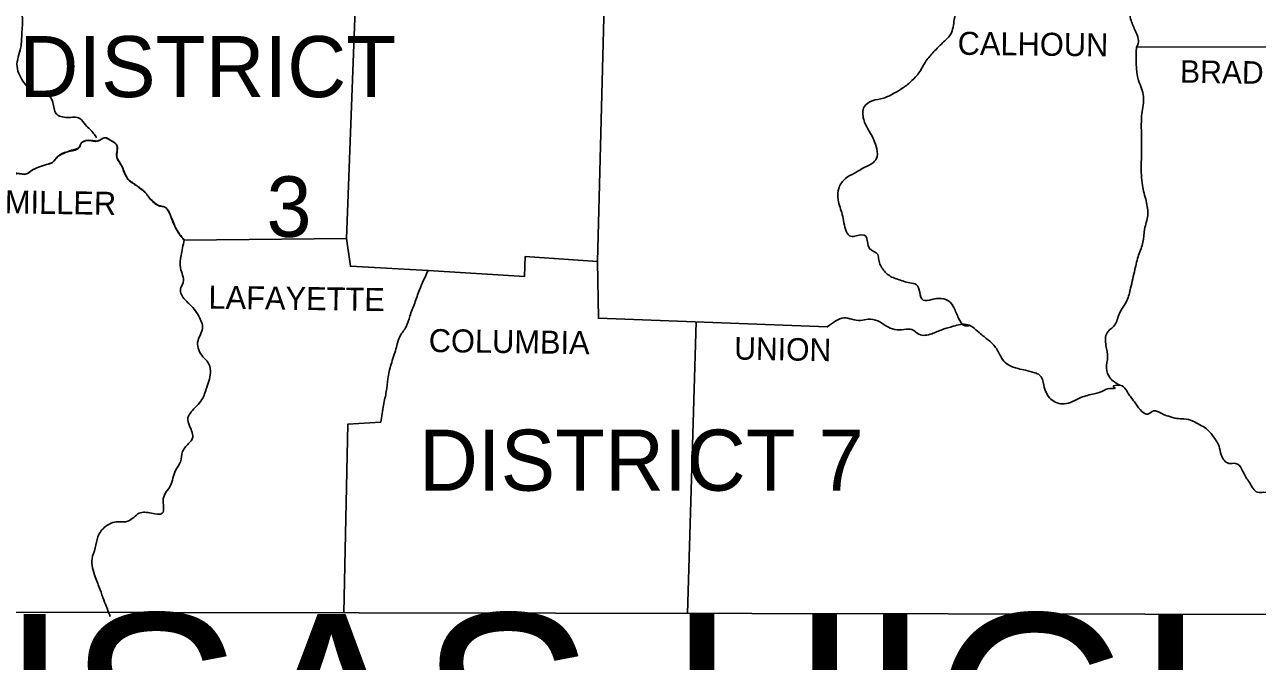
# Model space of a CAD drawing. Extents: x 3046 to 131673, y -8885 to 10756.
# Drawn here: x 64530 to 66781, y 4994 to 6157 of the extents above; entities that cross this region are included whole.
import ezdxf

# ---------------------------------------------------------------- set-up
doc = ezdxf.new("R2010")
doc.units = 0
for name, color, linetype in [('1', 7, 'Continuous'), ('2', 7, 'Continuous'), ('3', 7, 'Continuous'), ('R_Annotation', 7, 'Continuous')]:
    doc.layers.add(name, color=color, linetype=linetype)

msp = doc.modelspace()

# ---------------------------------------------------------------- linework, layer by layer
at = {"layer": '1'}
for points in [[(65157.419338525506, 6478.611953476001), (65155.46252490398, 6283.908996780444), (65137.851202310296, 6281.952183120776), (65118.283065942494, 5766.331790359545)], [(65588.89674506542, 6217.377333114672), (65576.17745635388, 5724.260297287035), (65444.09253611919, 5733.06595852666), (65443.11412921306, 5696.86490635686), (65267.00090220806, 5707.62738140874)], [(66560.45471461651, 6115.623024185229), (67002.69459609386, 6116.601431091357)], [(64421.65741198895, 5874.934947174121), (64423.614225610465, 5083.403831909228), (68009.47521109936, 5077.533390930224)], [(65267.00090220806, 5707.62738140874), (65125.13191359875, 5715.454635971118), (65118.283065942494, 5766.331790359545), (64821.82580016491, 5763.396570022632)], [(65995.91398108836, 5604.894665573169), (65578.13427001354, 5620.54917462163), (65576.08045633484, 5724.266763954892)], [(65756.26641412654, 5613.874433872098), (65740.74359051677, 5081.247549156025)], [(65180.901102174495, 5430.73825199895), (65120.23987956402, 5426.824624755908), (65113.391031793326, 5082.425425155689)]]:
    msp.add_lwpolyline(points, dxfattribs=at)
for points in [[(64352.190527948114, 6825.946373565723), (64357.08256194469, 6796.594169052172), (64365.8882234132, 6771.155591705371), (64366.86663012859, 6751.587455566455), (64375.6722915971, 6722.2352509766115), (64375.6722915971, 6711.472775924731), (64378.607512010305, 6689.947825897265), (64374.69388469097, 6678.2069442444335), (64379.585918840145, 6654.7251806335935), (64378.607512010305, 6637.11385784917), (64378.607512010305, 6622.437755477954), (64379.585918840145, 6597.977585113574), (64387.41317324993, 6576.452635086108), (64395.24042777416, 6544.16521015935), (64400.13246199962, 6527.532294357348), (64407.95971652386, 6502.09371708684), (64412.851750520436, 6470.7846988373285), (64413.830157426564, 6447.302935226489), (64411.87334380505, 6425.777985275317), (64417.7437847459, 6401.317814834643), (64428.5062596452, 6376.857644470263), (64442.203955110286, 6353.375880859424), (64458.83687095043, 6326.9588968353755), (64470.57775275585, 6306.41235356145), (64485.25385512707, 6283.908996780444), (64496.99473693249, 6265.319267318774), (64514.606059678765, 6241.837503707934), (64522.433314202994, 6222.2693672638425), (64522.433314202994, 6194.873976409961), (64526.3469413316, 6169.435399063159), (64525.368534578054, 6141.061601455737), (64523.41172095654, 6115.623024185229), (64516.56287330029, 6080.400378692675), (64521.454907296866, 6063.767462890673), (64540.04463679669, 6039.307292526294), (64551.785518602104, 6032.458444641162), (64572.33206187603, 6028.544817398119), (64582.11613005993, 6014.847121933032), (64587.98657096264, 5994.300578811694), (64608.53311408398, 5987.451731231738), (64631.03647082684, 5985.49491757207), (64641.79894587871, 5973.75403576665), (64656.475048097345, 5958.099526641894), (64661.36708228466, 5950.272272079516)], [(66381.40626708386, 6507.964157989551), (66403.90962378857, 6493.2880556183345), (66422.49935344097, 6473.719919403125), (66436.19704890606, 6459.0438170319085), (66445.00271018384, 6442.410901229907), (66456.7435920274, 6422.842764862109), (66473.3765078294, 6385.663305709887), (66488.05261020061, 6372.944017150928), (66508.59915332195, 6360.22472843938), (66521.31844207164, 6351.419067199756), (66534.03773059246, 6323.04526951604), (66539.90817149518, 6294.671471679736), (66550.67064643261, 6269.23289463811), (66555.56268058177, 6249.664758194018), (66546.75701915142, 6230.096621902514), (66544.8002055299, 6190.960349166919), (66550.67064643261, 6164.543365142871), (66558.49790099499, 6144.975228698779), (66563.3899351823, 6122.471871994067), (66560.45471461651, 6115.623024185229)], [(66237.08427846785, 6257.806639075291), (66234.64524447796, 6196.830789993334), (66227.79639682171, 6166.5001787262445), (66220.94754901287, 6139.104787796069), (66206.27144683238, 6123.450278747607), (66190.61693770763, 6107.795769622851), (66175.94083552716, 6090.184446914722), (66163.2215468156, 6068.659496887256), (66150.50225825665, 6054.961801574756), (66133.86934222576, 6041.264106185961), (66117.23642638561, 6031.4800379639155), (66098.6466969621, 6022.67437649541), (66078.10015365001, 6017.782342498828), (66063.42405146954, 6007.019867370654), (66062.44564456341, 5983.538103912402), (66079.07856055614, 5950.272272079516), (66084.949001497, 5934.61776295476), (66086.90581515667, 5916.028033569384), (66080.05696730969, 5905.2655584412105), (66064.40245818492, 5896.459897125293), (66045.8127287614, 5885.697422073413), (66029.17981292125, 5875.913353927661), (66017.43893111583, 5859.280438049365), (66015.48211745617, 5836.777081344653), (66023.3093719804, 5810.360097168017), (66026.24459235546, 5794.705588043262), (66038.96388110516, 5770.245417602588), (66048.7479492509, 5771.223824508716), (66066.3592718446, 5770.245417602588), (66068.31608550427, 5765.3533836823), (66069.2944924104, 5760.461349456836), (66073.20811969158, 5747.7420608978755), (66087.88422187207, 5736.979585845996), (66089.84103549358, 5727.19551762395), (66098.6466969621, 5708.60578816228), (66113.32279914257, 5695.88649960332), (66124.08527408, 5691.972872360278), (66146.58863097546, 5685.12402455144), (66158.32951278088, 5682.188804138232), (66171.04880133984, 5653.815006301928), (66186.70331042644, 5654.793413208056), (66198.44419223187, 5656.750226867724), (66218.01232863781, 5651.858192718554), (66226.81798991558, 5640.117311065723), (66235.62365138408, 5620.54917462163), (66247.36453318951, 5606.851479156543), (66255.19178771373, 5606.851479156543)], [(66560.45471461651, 6115.623024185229), (66564.3683418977, 6054.961801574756), (66573.17400332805, 6025.609597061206), (66570.23878280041, 5994.300578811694), (66569.26037604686, 5963.9699675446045), (66569.26037604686, 5936.574576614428), (66569.26037604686, 5910.157592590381), (66569.26037604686, 5882.7622016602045), (66571.21718970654, 5863.194065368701), (66578.06603736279, 5834.820267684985), (66581.00125792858, 5808.403283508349), (66575.13081698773, 5782.9647063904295), (66572.19559642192, 5759.4829427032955), (66564.3683418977, 5736.0011790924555), (66557.51949424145, 5709.584195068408), (66549.69223971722, 5675.339956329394), (66542.84339187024, 5652.836599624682), (66529.14569659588, 5629.354835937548), (66520.34003516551, 5607.829885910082), (66506.64233970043, 5594.132190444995), (66504.68552604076, 5570.650426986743), (66507.62074660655, 5549.125477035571), (66505.66393294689, 5529.557340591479), (66512.512780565, 5510.967610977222), (66530.12410331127, 5498.2483224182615)], [(64421.65741198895, 5874.934947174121), (64455.90165057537, 5889.611049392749), (64470.57775275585, 5884.719015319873), (64483.2970414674, 5871.999726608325), (64497.97314368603, 5871.999726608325), (64505.80039821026, 5883.740608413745), (64520.47650058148, 5884.719015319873), (64532.2173822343, 5883.740608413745), (64544.936670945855, 5891.567862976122), (64555.69914588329, 5896.459897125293), (64570.37524825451, 5901.351931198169), (64581.1377231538, 5905.2655584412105), (64590.9217913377, 5916.028033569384), (64608.53311408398, 5924.833694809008), (64629.07965716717, 5931.682542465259), (64634.95009810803, 5941.466610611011), (64644.73416629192, 5945.380237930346), (64664.30230265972, 5944.401831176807), (64677.02159121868, 5950.272272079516), (64687.78406630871, 5945.380237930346), (64697.56813445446, 5938.531390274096), (64699.52494811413, 5913.092813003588), (64707.352202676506, 5899.395117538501), (64719.09308452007, 5874.934947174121), (64735.726000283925, 5862.215658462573), (64751.380509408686, 5849.496369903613), (64757.25095034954, 5841.669115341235), (64773.88386618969, 5826.993013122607), (64788.55996852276, 5822.100978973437), (64795.408816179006, 5811.338503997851), (64806.1712910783, 5785.899926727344), (64821.82580016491, 5763.396570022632)], [(64821.82580016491, 5763.396570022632), (64815.955359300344, 5735.0227721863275), (64814.97695254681, 5712.519415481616), (64819.86898654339, 5686.102431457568), (64814.97695254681, 5673.38314274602), (64822.804207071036, 5654.793413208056), (64837.48030928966, 5640.117311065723), (64848.24278434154, 5624.4628019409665), (64855.09163203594, 5601.959445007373), (64846.285970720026, 5576.520867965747), (64856.07003894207, 5550.103883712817), (64864.87570018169, 5540.319815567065), (64869.767734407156, 5524.665306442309), (64862.918886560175, 5494.334695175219), (64854.1132252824, 5471.831338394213), (64834.5450889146, 5449.327981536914), (64828.674648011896, 5438.565506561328), (64831.60986834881, 5423.889404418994), (64836.501902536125, 5400.40764073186), (64831.60986834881, 5393.558792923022), (64818.89057978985, 5376.92587712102), (64814.97695254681, 5358.33614765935), (64806.1712910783, 5342.681638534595), (64796.387223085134, 5314.30784069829), (64783.66793433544, 5290.826077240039), (64781.711120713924, 5264.409093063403), (64762.142984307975, 5264.409093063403), (64739.63962760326, 5264.409093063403), (64719.09308452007, 5249.7329908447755), (64700.503354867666, 5248.754583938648), (64677.99999812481, 5239.948922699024), (64664.30230265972, 5221.359193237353), (64659.41026862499, 5200.812649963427), (64653.539827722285, 5181.2445135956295), (64659.41026862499, 5147.978681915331), (64668.21592990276, 5124.496918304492), (64675.06477755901, 5105.90718861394), (64686.805659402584, 5075.57657734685)], [(65180.901102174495, 5430.73825199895), (65185.79313636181, 5462.047270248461), (65190.68517035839, 5486.5074406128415), (65193.62039088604, 5509.989204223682), (65199.49083182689, 5536.406188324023), (65208.296493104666, 5564.779986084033), (65216.123747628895, 5588.2617496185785), (65226.88622252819, 5604.894665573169), (65233.73507037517, 5624.4628019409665), (65242.540731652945, 5647.944565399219), (65251.34639312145, 5672.40473599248), (65267.00090220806, 5707.62738140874)], [(65995.91398108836, 5604.894665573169), (66011.56849017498, 5615.657140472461), (66026.24459235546, 5621.5275813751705), (66040.92069472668, 5618.592361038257), (66056.5752036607, 5616.635547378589), (66070.27289912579, 5618.592361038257), (66087.88422187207, 5615.657140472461), (66102.56032420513, 5606.851479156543), (66119.19324004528, 5600.0026314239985), (66135.82615588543, 5600.0026314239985), (66150.50225825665, 5600.0026314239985), (66163.2215468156, 5591.196970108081), (66186.70331042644, 5592.175376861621), (66206.27144683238, 5600.0026314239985), (66225.83958316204, 5605.873072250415), (66252.25656722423, 5608.80829281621), (66275.73833087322, 5592.175376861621), (66292.37124671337, 5578.477681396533), (66306.06894214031, 5562.823172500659), (66315.85301032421, 5545.2118497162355), (66326.6154852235, 5535.427781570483), (66344.22680796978, 5528.578933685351), (66357.92450343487, 5525.643713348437), (66374.55741946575, 5520.7516791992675), (66383.36308070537, 5516.838051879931), (66391.19033526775, 5498.2483224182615), (66403.90962378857, 5472.809745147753), (66428.36979438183, 5464.004083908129), (66458.70040564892, 5475.744965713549), (66483.16057605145, 5482.593813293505), (66500.77189875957, 5488.46425427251), (66511.53437388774, 5492.377881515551), (66521.31844207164, 5493.356288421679), (66518.38322150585, 5495.313102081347), (66530.12410331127, 5498.2483224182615), (66540.88657824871, 5490.421067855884), (66547.73542605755, 5479.658592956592), (66559.47630790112, 5464.004083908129), (66570.23878280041, 5450.306388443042), (66581.00125792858, 5445.414354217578), (66591.76373282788, 5451.2847951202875), (66606.43983500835, 5446.392761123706), (66619.15912375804, 5441.500726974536), (66633.83522593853, 5437.587099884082), (66646.55451465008, 5436.608692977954), (66663.18743045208, 5432.695065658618), (66675.90671904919, 5425.846218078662), (66687.64760089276, 5418.99737019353), (66699.38848269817, 5406.27808163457), (66711.12936450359, 5386.7099453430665), (66715.04299178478, 5371.05543621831), (66728.74068724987, 5355.400927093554), (66741.45997596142, 5355.400927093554), (66760.0497054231, 5329.962349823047), (66766.89855307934, 5320.178281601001), (66781.57465545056, 5302.56695889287), (66792.33713034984, 5302.56695889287), (66812.88367347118, 5298.653331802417)]]:
    msp.add_spline(points, degree=3, dxfattribs=at)
at = {"layer": 'R_Annotation'}
msp.add_line((64821.82580016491, 5763.396570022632), (65118.283065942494, 5766.331790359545), dxfattribs=at)
msp.add_lwpolyline([(65118.283065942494, 5766.331790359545), (65137.851202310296, 6281.952183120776), (65155.46252490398, 6283.908996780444), (65157.41431318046, 6478.111931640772)], dxfattribs=at)
msp.add_spline([(64422.70489375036, 5875.762733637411), (64430.772422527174, 5881.300332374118), (64439.055965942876, 5885.515487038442), (64447.46316246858, 5888.316343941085), (64451.684267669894, 5889.1577064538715), (64455.90165057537, 5889.611049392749), (64459.55544959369, 5889.341318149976), (64463.254697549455, 5888.264884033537), (64466.9464475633, 5886.638524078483), (64470.57775275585, 5884.719015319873), (64474.22581250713, 5881.84193745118), (64477.19919592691, 5878.289693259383), (64480.04167993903, 5874.772287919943), (64483.2970414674, 5871.999726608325), (64490.611852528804, 5870.38422223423), (64494.539228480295, 5870.8442190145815), (64497.97314368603, 5871.999726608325), (64500.16966668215, 5874.5058688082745), (64501.58026906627, 5878.25179409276), (64503.14412239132, 5881.806906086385), (64505.80039821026, 5883.740608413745), (64509.467524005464, 5884.283980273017), (64513.13790549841, 5884.597624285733), (64516.808558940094, 5884.727362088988), (64520.47650058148, 5884.719015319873), (64523.41388130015, 5884.3910291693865), (64526.35180266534, 5883.812605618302), (64530.75319876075, 5883.479551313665), (64531.48552894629, 5883.578457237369), (64532.2173822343, 5883.740608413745), (64535.662701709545, 5885.222733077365), (64538.75523989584, 5887.350551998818), (64541.758671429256, 5889.630212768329), (64544.936670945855, 5891.567862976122), (64547.58843521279, 5892.860173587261), (64550.25058661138, 5894.153550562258), (64555.69914588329, 5896.459897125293), (64570.37524825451, 5901.351931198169), (64581.1377231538, 5905.2655584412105), (64583.983382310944, 5907.3571858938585), (64586.16158621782, 5910.381345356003), (64588.273875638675, 5913.538230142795), (64590.9217913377, 5916.028033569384), (64599.59016419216, 5920.722356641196), (64608.53311408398, 5924.833694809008), (64613.611445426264, 5926.688179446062), (64618.84536168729, 5928.177223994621), (64624.05978991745, 5929.706715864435), (64629.07965716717, 5931.682542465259), (64630.972642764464, 5933.590616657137), (64632.05419493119, 5936.356302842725), (64633.116088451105, 5939.2311258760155), (64634.95009810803, 5941.466610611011), (64637.28218501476, 5942.866234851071), (64639.690248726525, 5943.986147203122), (64644.73416629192, 5945.380237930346), (64649.6719964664, 5945.560966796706), (64654.7022717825, 5945.0118671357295), (64659.64052844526, 5944.402351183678), (64664.30230265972, 5944.401831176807), (64667.487259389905, 5945.663915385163), (64670.6651086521, 5947.879706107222), (64673.84137705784, 5949.824169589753), (64677.02159121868, 5950.272272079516), (64682.401482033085, 5948.295230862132), (64687.78406630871, 5945.380237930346), (64693.00957465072, 5942.386166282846), (64695.395566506, 5940.6674813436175), (64696.51144639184, 5939.664250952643), (64697.56813445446, 5938.531390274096), (64699.78376124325, 5932.707550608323), (64699.25950708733, 5926.034450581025), (64698.378770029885, 5919.250176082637), (64699.52494811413, 5913.092813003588), (64701.43373121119, 5909.655069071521), (64703.44064784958, 5906.245452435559), (64705.446528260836, 5902.835092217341), (64707.352202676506, 5899.395117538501), (64710.04227411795, 5893.147772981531), (64712.36978280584, 5886.65524926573), (64716.907163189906, 5877.550657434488), (64717.94364984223, 5876.207489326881), (64719.09308452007, 5874.934947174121), (64723.02543811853, 5871.414373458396), (64727.230172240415, 5868.298034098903), (64731.52459144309, 5865.32032909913), (64735.726000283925, 5862.215658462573), (64743.61651582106, 5855.938539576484), (64751.380509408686, 5849.496369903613), (64753.03185432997, 5847.718360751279), (64754.42166843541, 5845.70455215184), (64755.75851326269, 5843.629838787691), (64757.25095034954, 5841.669115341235), (64765.19999228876, 5833.874596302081), (64769.47753805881, 5830.341582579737), (64773.88386618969, 5826.993013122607), (64777.407294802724, 5825.487299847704), (64781.39752656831, 5824.851298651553), (64785.29995372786, 5824.0631461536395), (64787.0449256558, 5823.292680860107), (64788.55996852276, 5822.100978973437), (64792.42674540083, 5816.977172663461), (64795.408816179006, 5811.338503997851), (64798.2125810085, 5805.012819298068), (64800.780839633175, 5798.624648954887), (64803.3537052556, 5792.23376181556), (64806.1712910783, 5785.899926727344), (64809.27019658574, 5779.82862433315), (64812.74241923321, 5774.072396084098), (64816.84270507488, 5768.604093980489), (64819.20797983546, 5765.969431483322), (64821.82580016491, 5763.396570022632)], degree=3, dxfattribs=at)

# ---------------------------------------------------------------- texts
at = {"layer": '2'}
for s, height, rotation, p in [('CALHOUN', 42.07344995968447, 359.36340559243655, (66233.66683772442, 6101.925328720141)), ('BRADLEY', 41.081345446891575, 359.144902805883, (66639.70566684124, 6051.048174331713)), ('MILLER', 42.061709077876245, 359.1319472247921, (64494.059516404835, 5812.316910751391)), ('LAFAYETTE', 42.061709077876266, 359.18387503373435, (64865.85410708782, 5638.160497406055)), ('COLUMBIA', 42.06170907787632, 359.212477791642, (65267.9793089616, 5558.909545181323)), ('UNION', 41.09308632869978, 358.9583722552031, (65825.67119483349, 5545.2118497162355))]:
    msp.add_text(s, height=height, rotation=rotation, dxfattribs=at).set_placement(p)
msp.add_text('ARKANSAS HIGHWAY DISTRICT 3', height=360, dxfattribs=at).set_placement((62949.61558449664, 4720.468611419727))
at = {"layer": '3'}
for s, height, p in [('DISTRICT', 111.53837717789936, (64520.960579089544, 6024.518902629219)), ('3', 110.55801354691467, (64972.006121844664, 5769.189795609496)), ('DISTRICT 7', 111.53837717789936, (65250.36798621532, 5305.502179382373))]:
    msp.add_text(s, height=height, dxfattribs=at).set_placement(p)

doc.saveas('drawing.dxf')
